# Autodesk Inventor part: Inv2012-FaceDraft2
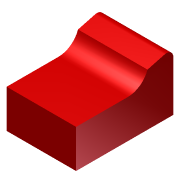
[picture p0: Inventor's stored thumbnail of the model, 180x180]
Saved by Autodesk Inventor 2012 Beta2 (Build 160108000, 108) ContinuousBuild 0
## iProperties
Created: 2011-02
Part Number: Inv2012-FaceDraft2
Material: Default
Document SubType Name: Modeling
Designer: ehttln
Density: 1 g/cm^3
Author: ehttln
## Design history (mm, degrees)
sketch "Sketch1"
  geometry: L1 (-23.559, -52.24)-(26.441, -52.24); L2 (26.441, -52.24)-(26.441, 17.76); L3 (26.441, 17.76)-(-23.559, 17.76); L4 (-23.559, 17.76)-(-23.559, -52.24); 1 further point
  constraints: 8 end point, 2 parallel, 1 horizontal, 1 perpendicular
  dimensions: "d0" = 50 distance of L2.end L3.end; "d1" = 70 distance of L3.end L1.start
extrude "Extrusion1" new body sketch "Sketch1" distance "d2" = 27.5; taper "d3" = 0 deg
sketch "Sketch7"
  geometry: L1 (26.441, 17.76)-(26.441, -52.24) reference; L2 (-23.559, 17.76)-(26.441, 17.76) reference; L3 (-23.559, 17.76)-(26.441, 17.76); L4 (26.441, 17.76)-(26.441, 0); L5 (26.441, 0)-(-23.559, 0); L6 (-23.559, 0)-(-23.559, 17.76); 1 further point
  constraints: 8 end point, 2 parallel, 1 horizontal, 1 perpendicular, 1 point on line
extrude "Extrusion2" join sketch "Sketch7" distance "d35" = 25; taper "d36" = 0 deg
fillet "Fillet4" dims "d37" = 15
workplane "Work Plane1"
split "Split1"
fillet "Fillet5" dims "d40" = 5
feature "FaceDraft8" dims angle "d41" = -15 deg
fillet "Fillet2" dims "d31" = 10
sketch "Sketch6"
  geometry: 5 further points
  constraints: 4 other
fillet "Fillet3" dims "d33" = 3
feature "FaceDraft6" dims angle "d34" = 15 deg
sketch "Sketch2"
  geometry: L1 (0, 0)-(-27.5, 0) reference; L2 (0, 0)-(0, 70) reference; L3 (0, 70)-(-27.5, 70) reference; L4 (-5, 70)-(-17.343, 0); 1 further point
  constraints: 2 end point, 2 point on line
  dimensions: "d24" = 5 distance from line of L2 L4.start; "d25" = 80 deg angle of L3 L4
sketch "Sketch3"
  geometry: L1 (0, 0)-(0, 27.5) reference; L2 (50, 17.343)-(0, 17.343); 1 further point
  constraints: 2 end point, 1 perpendicular, 1 point on line
feature "FaceDraft1" dims angle "d26" = 10 deg
feature "FaceDraft2" dims angle "d27" = 10 deg, "d30" = 30 deg
sketch "Sketch5"
  geometry: L1 (0, 27.5)-(0, 0) reference; L2 (50, 22.5)-(0, 22.5); 1 further point
  constraints: 2 end point, 1 perpendicular, 1 point on line
feature "FaceDraft3" sketch "Sketch5" dims angle "d28" = 10 deg
sketch "Sketch4"
  geometry: L1 (17.343, -70)-(27.5, -68.209) reference; L2 (5, 0)-(17.343, -70); 1 further point
  constraints: 2 end point, 1 perpendicular
feature "FaceDraft4" sketch "Sketch4" dims angle "d29" = 10 deg
body "Solid1"
other parameters: "d39" = -15
